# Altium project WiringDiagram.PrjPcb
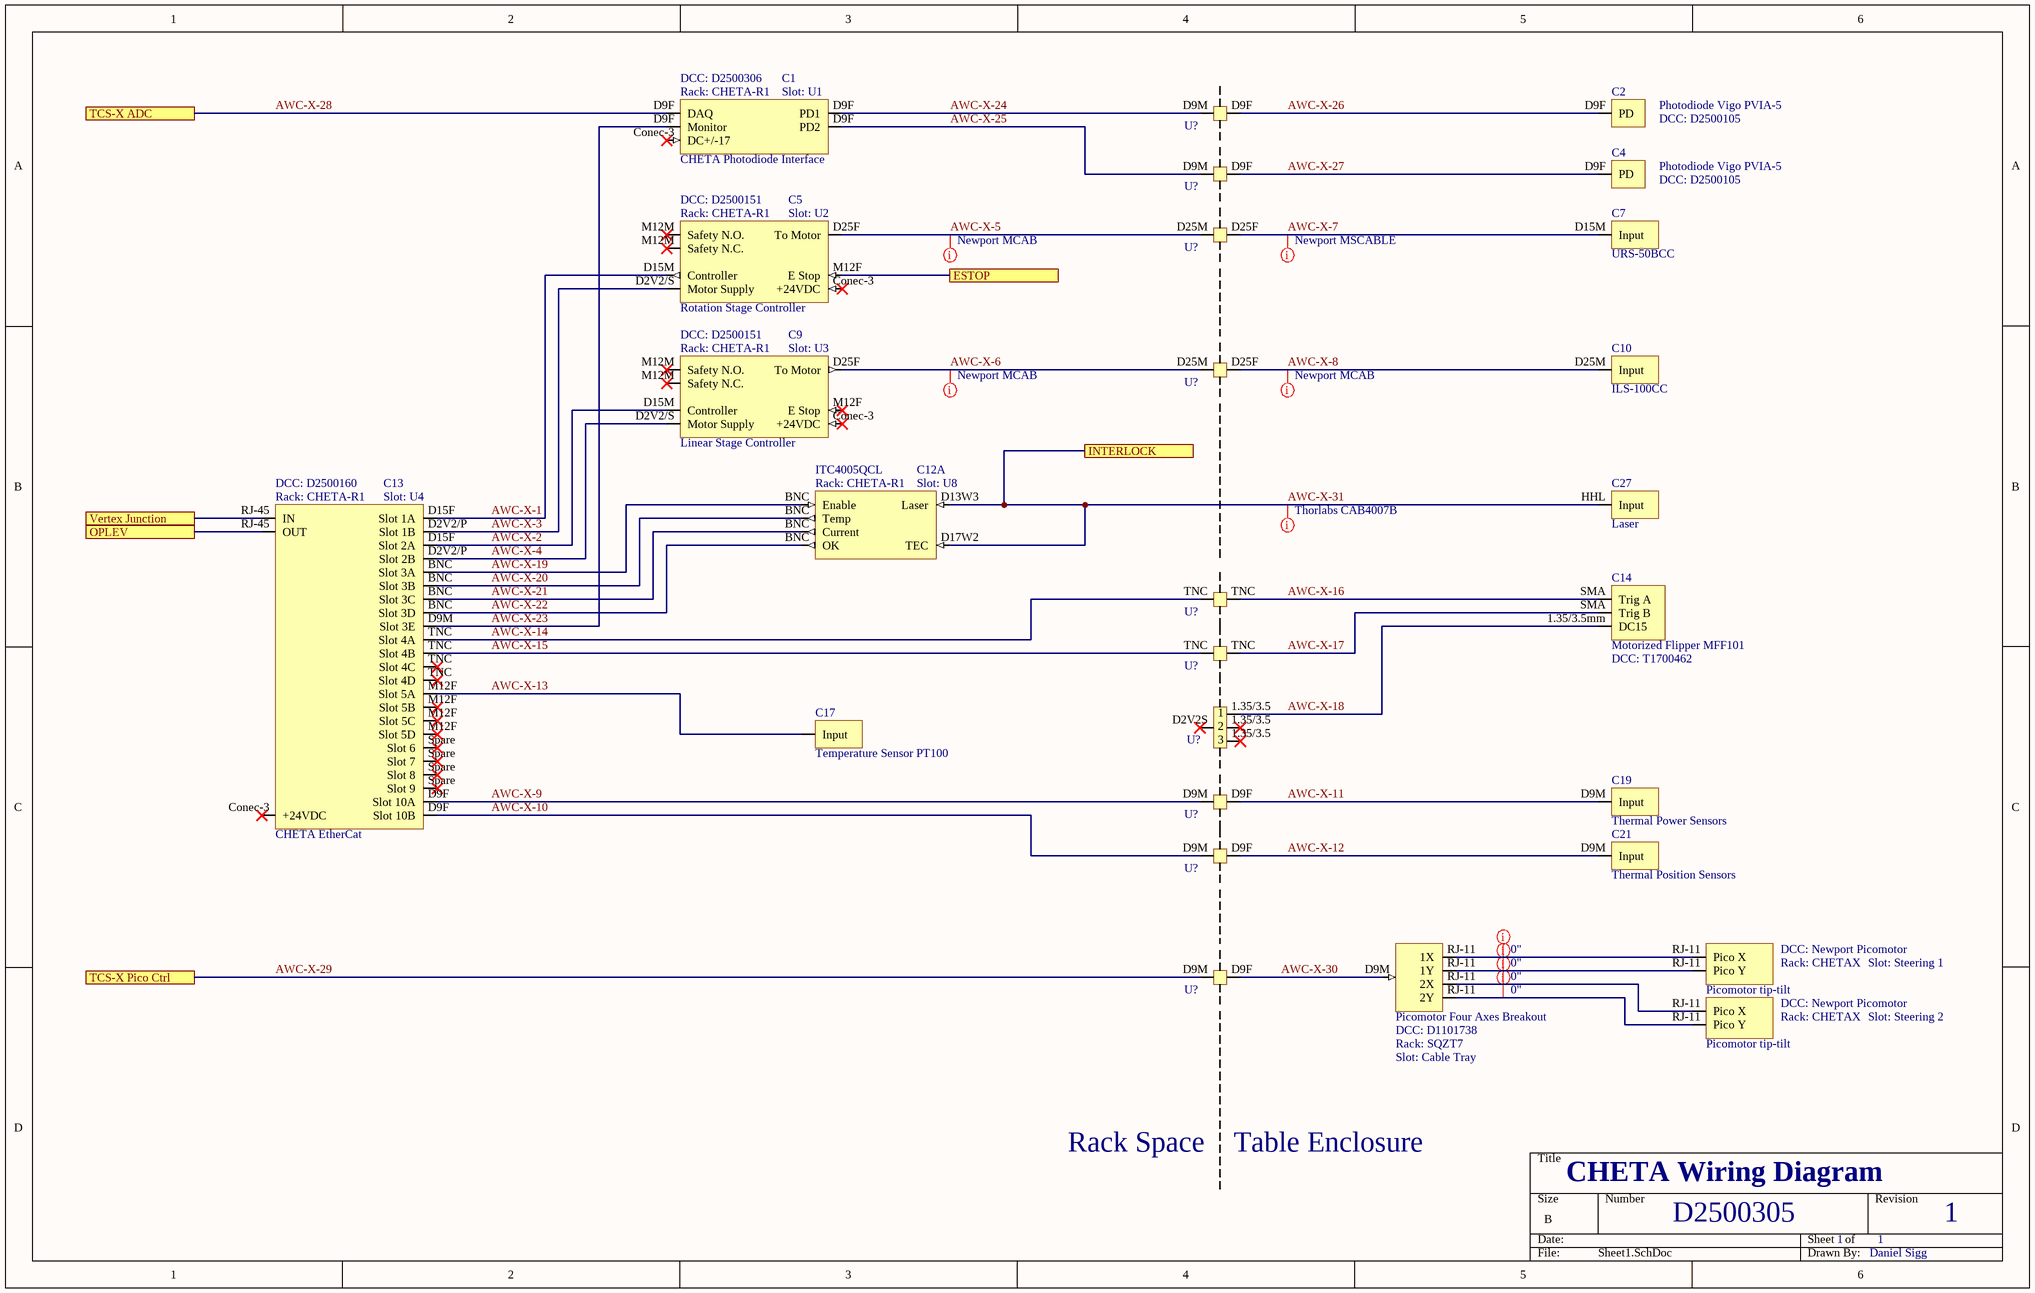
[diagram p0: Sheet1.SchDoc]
DocumentNumber: D2500305; DrawnBy: Daniel Sigg; Revision: 1; Title: CHETA Wiring Diagram
1 sheet, 27 parts. Net scope: flat (ports and power ports of the same name join across sheets).

## Sheet Sheet1.SchDoc: CHETA Wiring Diagram
size B; SheetNumber: 1; SheetTotal: 1

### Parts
C1  CHETA Photodiode Interface  DCC: D2500306  Rack: CHETA-R1  Slot: U1
C2  Photodiode Vigo PVIA-5  DCC: D2500105
C3  Slot: U?  (hidden comment: Patch Panel (D9))
C4  Photodiode Vigo PVIA-5  DCC: D2500105
C5  Rotation Stage Controller  DCC: D2500151  Rack: CHETA-R1  Slot: U2
C6  Slot: U?  (hidden comment: Patch Panel (D9))
C7  URS-50BCC
C8  Slot: U?  (hidden comment: Patch Panel (D25))
C9  Linear Stage Controller  DCC: D2500151  Rack: CHETA-R1  Slot: U3
C10  ILS-100CC
C11  Slot: U?  (hidden comment: Patch Panel (D25))
C12  ITC4005QCL  Rack: CHETA-R1  Slot: U8  (part A of 2)
C13  CHETA EtherCat  DCC: D2500160  Rack: CHETA-R1  Slot: U4
C14  Motorized Flipper MFF101  DCC: T1700462
C15  Slot: U?  (hidden comment: Patch Panel (TNC))
C16  Slot: U?  (hidden comment: Patch Panel (TNC))
C17  Temperature Sensor PT100
C18  Slot: U?  (hidden comment: Patch Panel Motorized Flipper)  (part G of 7)
C19  Thermal Power Sensors
C20  Slot: U?  (hidden comment: Patch Panel (D9))
C21  Thermal Position Sensors
C22  Slot: U?  (hidden comment: Patch Panel (D9))
C23  Picomotor Four Axes Breakout  DCC: D1101738  Rack: SQZT7  Slot: Cable Tray
C24  Picomotor tip-tilt  DCC: Newport Picomotor  Rack: CHETAX  Slot: Steering 1
C25  Picomotor tip-tilt  DCC: Newport Picomotor  Rack: CHETAX  Slot: Steering 2
C26  Slot: U?  (hidden comment: Patch Panel (D9))
C27  Laser

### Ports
ESTOP, INTERLOCK, OPLEV, TCS-X ADC, TCS-X Pico Ctrl, Vertex Junction

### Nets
AWC-X-1: C5.D15M(Controller) C13.D15F(Slot_1A)
AWC-X-2: C9.D15M(Controller) C13.D15F(Slot_2A)
AWC-X-3: C5.D2V2/S(Motor_Supply) C13.D2V2/P(Slot_1B)
AWC-X-4: C9.D2V2/S(Motor_Supply) C13.D2V2/P(Slot_2B)
AWC-X-5: C5.D25F(To_Motor) C8.D25M
AWC-X-6: C9.D25F(To_Motor) C11.D25M
AWC-X-7: C7.D15M(Input) C8.D25F
AWC-X-8: C10.D25M(Input) C11.D25F
AWC-X-9: C13.D9F(Slot_10A) C20.D9M
AWC-X-10: C13.D9F(Slot_10B) C22.D9M
AWC-X-11: C19.D9M(Input) C20.D9F
AWC-X-12: C21.D9M(Input) C22.D9F
AWC-X-13: C13.M12F(Slot_5A) C17.?1(Input)
AWC-X-14: C13.TNC(Slot_4A) C15.TNC
AWC-X-15: C13.TNC(Slot_4B) C16.TNC
AWC-X-16: C14.SMA(Trig_A) C15.TNC
AWC-X-17: C14.SMA(Trig_B) C16.TNC
AWC-X-18: C14.1.35/3.5mm(DC15) C18.1.35/3.5(Barrel2)
AWC-X-19: C12.BNC(Enable) C13.BNC(Slot_3A)
AWC-X-20: C12.BNC(Temp) C13.BNC(Slot_3B)
AWC-X-21: C12.BNC(Current) C13.BNC(Slot_3C)
AWC-X-22: C12.BNC(OK) C13.BNC(Slot_3D)
AWC-X-23: C1.D9F(Monitor) C13.D9M(Slot_3E)
AWC-X-24: C1.D9F(PD1) C3.D9M
AWC-X-25: C1.D9F(PD2) C6.D9M
AWC-X-26: C2.D9F(PD) C3.D9F
AWC-X-27: C4.D9F(PD) C6.D9F
AWC-X-28: C1.D9F(DAQ) ; port TCS-X ADC
AWC-X-29: C26.D9M ; port TCS-X Pico Ctrl
AWC-X-30: C23.D9M(IN) C26.D9F
AWC-X-31: C12.D13W3(Laser) C12.D17W2(TEC) C27.HHL(Input) ; port INTERLOCK
NetC5_M12F: C5.M12F(E_Stop) ; port ESTOP
NetC13_RJ-45: C13.RJ-45(IN) ; port Vertex Junction
NetC13_RJ-45: C13.RJ-45(OUT) ; port OPLEV  [a separate net that carries the same name]
NetC23_RJ-11: C23.RJ-11(1X) C24.RJ-11(Pico_X)
NetC23_RJ-11: C23.RJ-11(1Y) C24.RJ-11(Pico_Y)  [a separate net that carries the same name]
NetC23_RJ-11: C23.RJ-11(2X) C25.RJ-11(Pico_X)  [a separate net that carries the same name]
NetC23_RJ-11: C23.RJ-11(2Y) C25.RJ-11(Pico_Y)  [a separate net that carries the same name]

Not connected (* = marked no-connect by the designer): C1 Conec-3(DC+/-17)*; C5 Conec-3(+24VDC)* M12M(Safety_N.O.)*; C9 Conec-3(+24VDC)* M12F(E_Stop)* M12M(Safety_N.O.)*; C13 Conec-3(+24VDC)* Spare(Slot_6)*; C18 D2V2S(Power)*

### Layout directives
DCC: MSCABLE; Cable: Newport MSCABLE: AWC-X-7
DCC: MCAB; Cable: Newport MCAB: AWC-X-5, AWC-X-6, AWC-X-8
Length: 0": NetC23_RJ-11
DCC: MCAB; Cable: Thorlabs CAB4007B: AWC-X-31

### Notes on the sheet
- Rack Space
- Table Enclosure

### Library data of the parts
C1 = Photodiode Interface CHETA: Serial: Sxxxxxxx; System: ISC
C2 C4 = Photodiode Vigo PVIA-5: Serial: Sxxxxxxx; System: TCS; Rack: CHETAX; Slot: U?
C3 C6 C20 C22 C26 = Patch Panel (D9): Serial: Sxxxxxxx; System: ISC; DCC: tbd; Rack: CHETAX
C5 C9 = Linear Stage Controller: Serial: Sxxxxxxx; System: ISC
C7 = Motor: Motor URS-50BCC; Serial: Sxxxxxxx; System: ISC; DCC: tbd; Rack: CHETAX; Slot: U?
C8 C11 = Patch Panel (D25): Serial: Sxxxxxxx; System: AWC; DCC: tbd; Rack: CHETAX
C10 = Motor: Motor ILS-100CC; Serial: Sxxxxxxx; System: ISC; DCC: tbd; Rack: CHETAX; Slot: U?
C12 = ITC4005QCL: Serial: Sxxxxxxx; System: ISC; DCC: T1700189
C13 = CHETA EtherCat: Serial: Sxxxxxxx; System: ISC
C14 = Motorized Flipper: Serial: Sxxxxxxx; System: ISC; Rack: CHETAX; Slot: U?
C15 C16 = Patch Panel (TNC): Serial: Sxxxxxxx; System: ISC; DCC: tbd; Rack: CHETAX
C17 = AOM: Serial: Sxxxxxxx; System: ISC; DCC: tbd; Rack: R?; Slot: U?
C18 = Patch Panel Motorized Flipper: Patch Panel (D1700169); Serial: Sxxxxxxx; System: ISC; Rack: CHETAX
C19 = AOM: Serial: Sxxxxxxx; System: ISC; DCC: tbd; Rack: CHETAX; Slot: U?
C21 = AOM: Thermal Power Sensors; Serial: Sxxxxxxx; System: ISC; DCC: tbd; Rack: CHETAX; Slot: U?
C23 = Picomotor Four Axes Breakout: Serial: Sxxxxxxx; System: ISC
C24 C25 = Picomotor 2-axes: Serial: Sxxxxxxx; System: ISC
C27 = Motor: Serial: Sxxxxxxx; System: ISC; DCC: tbd; Rack: CHETAX; Slot: U?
